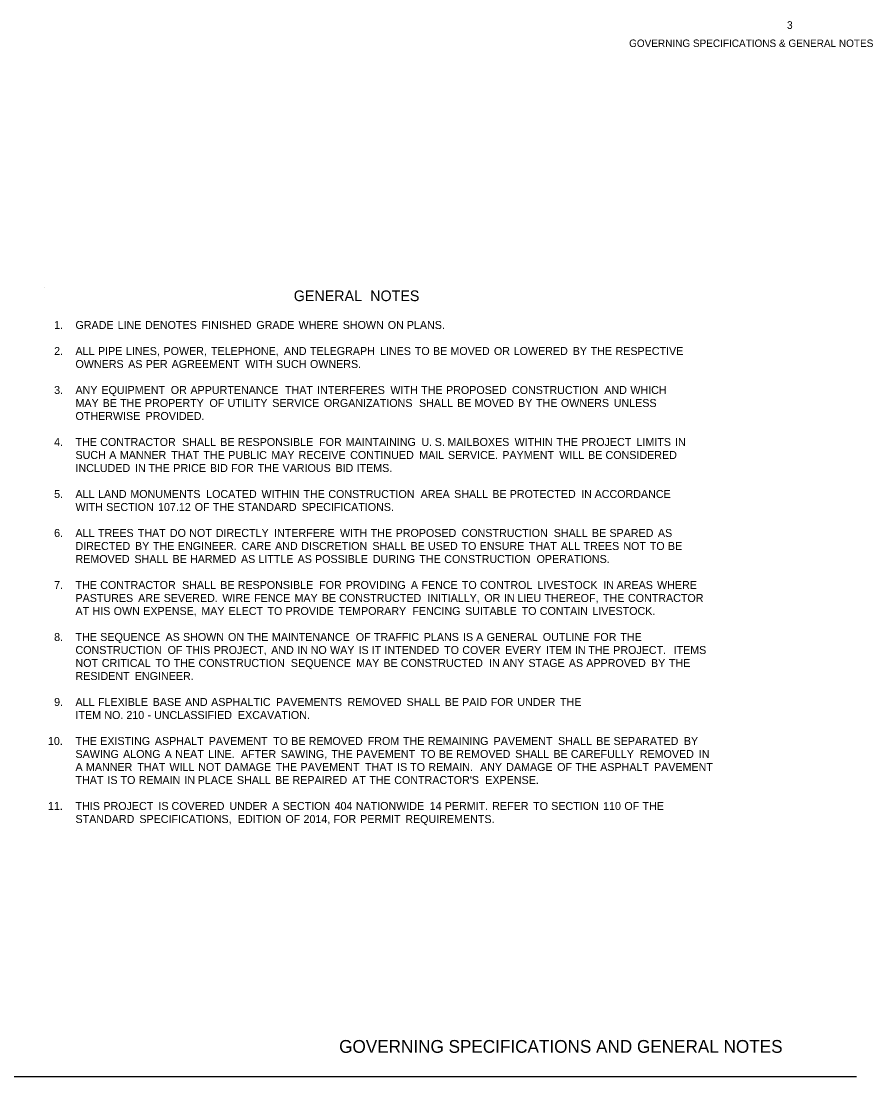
# Model space of a CAD drawing. Extents: x 1334737.6 to 1334769.5, y 402732.2 to 402752.6.
# Drawn here: x 1334753.53 to 1334769.49, y 402732.19 to 402751.98 of the extents above; entities that cross this region are included whole.
import ezdxf

# ---------------------------------------------------------------- set-up
doc = ezdxf.new("R2010")
doc.units = 0
doc.layers.add('Default', color=7, linetype='Continuous')
doc.layers.add('R_No Plot', color=7, linetype='Continuous')

msp = doc.modelspace()

# ---------------------------------------------------------------- linework, layer by layer
at = {"layer": 'Default'}
msp.add_line((1334753.96, 402746.996), (1334753.96, 402746.996), dxfattribs=at)
at = {"layer": 'R_No Plot'}
msp.add_line((1334769.182, 402732.187), (1334737.564, 402732.187), dxfattribs=at)

# ---------------------------------------------------------------- texts
at = {"layer": 'Default'}
for s, height, p in [('GENERAL', 0.2, (1334758.636, 402746.732)), (' NOTES', 0.2, (1334759.994, 402746.732)), ('1.', 0.15, (1334754.145, 402746.21)), ('GRADE', 0.15, (1334754.545, 402746.21)), (' LINE', 0.15, (1334755.279, 402746.21)), (' DENOTES', 0.15, (1334755.792, 402746.21)), (' FINISHED', 0.15, (1334756.853, 402746.21)), (' GRADE', 0.15, (1334757.878, 402746.21)), (' WHERE', 0.15, (1334758.67, 402746.21)), (' SHOWN', 0.15, (1334759.498, 402746.21)), (' ON', 0.15, (1334760.342, 402746.21)), (' PLANS.', 0.15, (1334760.698, 402746.21)), ('2.', 0.15, (1334754.145, 402745.722)), ('ALL', 0.15, (1334754.545, 402745.722)), (' PIPE', 0.15, (1334754.911, 402745.722)), (' LINES,', 0.15, (1334755.435, 402745.722)), (' POWER,', 0.15, (1334756.139, 402745.722)), (' TELEPHONE,', 0.15, (1334757.028, 402745.722)), (' AND', 0.15, (1334758.396, 402745.722)), (' TELEGRAPH', 0.15, (1334758.885, 402745.722)), (' LINES', 0.15, (1334760.196, 402745.722)), (' TO', 0.15, (1334760.849, 402745.722)), (' BE', 0.15, (1334761.189, 402745.722)), (' MOVED', 0.15, (1334761.516, 402745.722)), (' OR', 0.15, (1334762.331, 402745.722)), (' LOWERED', 0.15, (1334762.701, 402745.722)), (' BY', 0.15, (1334763.808, 402745.722)), (' THE', 0.15, (1334764.144, 402745.722)), (' RESPECTIVE', 0.15, (1334764.61, 402745.722)), ('OWNERS', 0.15, (1334754.545, 402745.478)), (' AS', 0.15, (1334755.477, 402745.478)), (' PER', 0.15, (1334755.804, 402745.478)), (' AGREEMENT', 0.15, (1334756.291, 402745.478)), (' WITH', 0.15, (1334757.672, 402745.478)), (' SUCH', 0.15, (1334758.249, 402745.478)), (' OWNERS.', 0.15, (1334758.884, 402745.478)), ('3.', 0.15, (1334754.145, 402744.991)), ('ANY', 0.15, (1334754.545, 402744.991)), (' EQUIPMENT', 0.15, (1334754.975, 402744.991)), (' OR', 0.15, (1334756.275, 402744.991)), (' APPURTENANCE', 0.15, (1334756.644, 402744.991)), (' THAT', 0.15, (1334758.415, 402744.991)), (' INTERFERES', 0.15, (1334759.017, 402744.991)), (' WITH', 0.15, (1334760.391, 402744.991)), (' THE', 0.15, (1334760.968, 402744.991)), (' PROPOSED', 0.15, (1334761.434, 402744.991)), (' CONSTRUCTION', 0.15, (1334762.669, 402744.991)), (' AND', 0.15, (1334764.399, 402744.991)), (' WHICH', 0.15, (1334764.888, 402744.991)), ('MAY', 0.15, (1334754.545, 402744.747)), (' BE', 0.15, (1334754.998, 402744.747)), (' THE', 0.15, (1334755.325, 402744.747)), (' PROPERTY', 0.15, (1334755.791, 402744.747)), (' OF', 0.15, (1334757, 402744.747)), (' UTILITY', 0.15, (1334757.34, 402744.747)), (' SERVICE', 0.15, (1334758.177, 402744.747)), (' ORGANIZATIONS', 0.15, (1334759.144, 402744.747)), (' SHALL', 0.15, (1334760.927, 402744.747)), (' BE', 0.15, (1334761.641, 402744.747)), (' MOVED', 0.15, (1334761.968, 402744.747)), (' BY', 0.15, (1334762.784, 402744.747)), (' THE', 0.15, (1334763.12, 402744.747)), (' OWNERS', 0.15, (1334763.586, 402744.747)), (' UNLESS', 0.15, (1334764.576, 402744.747)), ('OTHERWISE', 0.15, (1334754.545, 402744.503)), (' PROVIDED.', 0.15, (1334755.803, 402744.503)), ('4.', 0.15, (1334754.145, 402744.016)), ('THE', 0.15, (1334754.545, 402744.016)), (' CONTRACTOR', 0.15, (1334754.953, 402744.016)), (' SHALL', 0.15, (1334756.487, 402744.016)), (' BE', 0.15, (1334757.202, 402744.016)), (' RESPONSIBLE', 0.15, (1334757.529, 402744.016)), (' FOR', 0.15, (1334759.055, 402744.016)), (' MAINTAINING', 0.15, (1334759.553, 402744.016)), (' U.', 0.15, (1334760.972, 402744.016)), (' S.', 0.15, (1334761.222, 402744.016)), (' MAILBOXES', 0.15, (1334761.46, 402744.016)), (' WITHIN', 0.15, (1334762.718, 402744.016)), (' THE', 0.15, (1334763.504, 402744.016)), (' PROJECT', 0.15, (1334763.97, 402744.016)), (' LIMITS', 0.15, (1334765.003, 402744.016)), (' IN', 0.15, (1334765.725, 402744.016)), ('SUCH', 0.15, (1334754.545, 402743.772)), (' A', 0.15, (1334755.122, 402743.772)), (' MANNER', 0.15, (1334755.321, 402743.772)), (' THAT', 0.15, (1334756.284, 402743.772)), (' THE', 0.15, (1334756.886, 402743.772)), (' PUBLIC', 0.15, (1334757.352, 402743.772)), (' MAY', 0.15, (1334758.159, 402743.772)), (' RECEIVE', 0.15, (1334758.67, 402743.772)), (' CONTINUED', 0.15, (1334759.637, 402743.772)), (' MAIL', 0.15, (1334760.93, 402743.772)), (' SERVICE.', 0.15, (1334761.47, 402743.772)), (' PAYMENT', 0.15, (1334762.488, 402743.772)), (' WILL', 0.15, (1334763.555, 402743.772)), (' BE', 0.15, (1334764.095, 402743.772)), (' CONSIDERED', 0.15, (1334764.422, 402743.772)), ('INCLUDED', 0.15, (1334754.545, 402743.528)), (' IN', 0.15, (1334755.605, 402743.528)), (' THE', 0.15, (1334755.856, 402743.528)), (' PRICE', 0.15, (1334756.322, 402743.528)), (' BID', 0.15, (1334757.01, 402743.528)), (' FOR', 0.15, (1334757.406, 402743.528)), (' THE', 0.15, (1334757.904, 402743.528)), (' VARIOUS', 0.15, (1334758.37, 402743.528)), (' BID', 0.15, (1334759.361, 402743.528)), (' ITEMS.', 0.15, (1334759.757, 402743.528)), ('5.', 0.15, (1334754.145, 402743.041)), ('ALL', 0.15, (1334754.545, 402743.041)), (' LAND', 0.15, (1334754.911, 402743.041)), (' MONUMENTS', 0.15, (1334755.517, 402743.041)), (' LOCATED', 0.15, (1334756.938, 402743.041)), (' WITHIN', 0.15, (1334757.975, 402743.041)), (' THE', 0.15, (1334758.761, 402743.041)), (' CONSTRUCTION', 0.15, (1334759.227, 402743.041)), (' AREA', 0.15, (1334760.957, 402743.041)), (' SHALL', 0.15, (1334761.586, 402743.041)), (' BE', 0.15, (1334762.301, 402743.041)), (' PROTECTED', 0.15, (1334762.627, 402743.041)), (' IN', 0.15, (1334763.967, 402743.041)), (' ACCORDANCE', 0.15, (1334764.218, 402743.041)), ('WITH', 0.15, (1334754.545, 402742.797)), (' SECTION', 0.15, (1334755.064, 402742.797)), (' 107.12', 0.15, (1334756.036, 402742.797)), (' OF', 0.15, (1334756.724, 402742.797)), (' THE', 0.15, (1334757.064, 402742.797)), (' STANDARD', 0.15, (1334757.53, 402742.797)), (' SPECIFICATIONS.', 0.15, (1334758.73, 402742.797)), ('6.', 0.15, (1334754.145, 402742.31)), ('ALL', 0.15, (1334754.545, 402742.31)), (' TREES', 0.15, (1334754.911, 402742.31)), (' THAT', 0.15, (1334755.657, 402742.31)), (' DO', 0.15, (1334756.258, 402742.31)), (' NOT', 0.15, (1334756.621, 402742.31)), (' DIRECTLY', 0.15, (1334757.118, 402742.31)), (' INTERFERE', 0.15, (1334758.211, 402742.31)), (' WITH', 0.15, (1334759.446, 402742.31)), (' THE', 0.15, (1334760.022, 402742.31)), (' PROPOSED', 0.15, (1334760.489, 402742.31)), (' CONSTRUCTION', 0.15, (1334761.724, 402742.31)), (' SHALL', 0.15, (1334763.453, 402742.31)), (' BE', 0.15, (1334764.168, 402742.31)), (' SPARED', 0.15, (1334764.495, 402742.31)), (' AS', 0.15, (1334765.404, 402742.31)), ('DIRECTED', 0.15, (1334754.545, 402742.066)), (' BY', 0.15, (1334755.605, 402742.066)), (' THE', 0.15, (1334755.942, 402742.066)), (' ENGINEER.', 0.15, (1334756.408, 402742.066)), (' CARE', 0.15, (1334757.601, 402742.066)), (' AND', 0.15, (1334758.23, 402742.066)), (' DISCRETION', 0.15, (1334758.72, 402742.066)), (' SHALL', 0.15, (1334760.053, 402742.066)), (' BE', 0.15, (1334760.768, 402742.066)), (' USED', 0.15, (1334761.095, 402742.066)), (' TO', 0.15, (1334761.724, 402742.066)), (' ENSURE', 0.15, (1334762.064, 402742.066)), (' THAT', 0.15, (1334762.985, 402742.066)), (' ALL', 0.15, (1334763.586, 402742.066)), (' TREES', 0.15, (1334764.01, 402742.066)), (' NOT', 0.15, (1334764.756, 402742.066)), (' TO', 0.15, (1334765.252, 402742.066)), (' BE', 0.15, (1334765.592, 402742.066)), ('REMOVED', 0.15, (1334754.545, 402741.822)), (' SHALL', 0.15, (1334755.594, 402741.822)), (' BE', 0.15, (1334756.309, 402741.822)), (' HARMED', 0.15, (1334756.635, 402741.822)), (' AS', 0.15, (1334757.591, 402741.822)), (' LITTLE', 0.15, (1334757.917, 402741.822)), (' AS', 0.15, (1334758.652, 402741.822)), (' POSSIBLE', 0.15, (1334758.978, 402741.822)), (' DURING', 0.15, (1334760.062, 402741.822)), (' THE', 0.15, (1334760.934, 402741.822)), (' CONSTRUCTION', 0.15, (1334761.4, 402741.822)), (' OPERATIONS.', 0.15, (1334763.13, 402741.822)), ('7.', 0.15, (1334754.145, 402741.335)), ('THE', 0.15, (1334754.545, 402741.335)), (' CONTRACTOR', 0.15, (1334754.953, 402741.335)), (' SHALL', 0.15, (1334756.487, 402741.335)), (' BE', 0.15, (1334757.202, 402741.335)), (' RESPONSIBLE', 0.15, (1334757.529, 402741.335)), (' FOR', 0.15, (1334759.055, 402741.335)), (' PROVIDING', 0.15, (1334759.553, 402741.335)), (' A', 0.15, (1334760.774, 402741.335)), (' FENCE', 0.15, (1334760.973, 402741.335)), (' TO', 0.15, (1334761.73, 402741.335)), (' CONTROL', 0.15, (1334762.07, 402741.335)), (' LIVESTOCK', 0.15, (1334763.146, 402741.335)), (' IN', 0.15, (1334764.38, 402741.335)), (' AREAS', 0.15, (1334764.63, 402741.335)), (' WHERE', 0.15, (1334765.388, 402741.335)), ('PASTURES', 0.15, (1334754.545, 402741.091)), (' ARE', 0.15, (1334755.664, 402741.091)), (' SEVERED.', 0.15, (1334756.142, 402741.091)), (' WIRE', 0.15, (1334757.242, 402741.091)), (' FENCE', 0.15, (1334757.836, 402741.091)), (' MAY', 0.15, (1334758.594, 402741.091)), (' BE', 0.15, (1334759.105, 402741.091)), (' CONSTRUCTED', 0.15, (1334759.431, 402741.091)), (' INITIALLY,', 0.15, (1334761.085, 402741.091)), (' OR', 0.15, (1334762.15, 402741.091)), (' IN', 0.15, (1334762.519, 402741.091)), (' LIEU', 0.15, (1334762.77, 402741.091)), (' THEREOF,', 0.15, (1334763.277, 402741.091)), (' THE', 0.15, (1334764.376, 402741.091)), (' CONTRACTOR', 0.15, (1334764.843, 402741.091)), ('AT', 0.15, (1334754.545, 402740.847)), (' HIS', 0.15, (1334754.809, 402740.847)), (' OWN', 0.15, (1334755.205, 402740.847)), (' EXPENSE,', 0.15, (1334755.759, 402740.847)), (' MAY', 0.15, (1334756.847, 402740.847)), (' ELECT', 0.15, (1334757.358, 402740.847)), (' TO', 0.15, (1334758.087, 402740.847)), (' PROVIDE', 0.15, (1334758.427, 402740.847)), (' TEMPORARY', 0.15, (1334759.417, 402740.847)), (' FENCING', 0.15, (1334760.802, 402740.847)), (' SUITABLE', 0.15, (1334761.79, 402740.847)), (' TO', 0.15, (1334762.85, 402740.847)), (' CONTAIN', 0.15, (1334763.19, 402740.847)), (' LIVESTOCK.', 0.15, (1334764.175, 402740.847)), ('8.', 0.15, (1334754.145, 402740.36)), ('THE', 0.15, (1334754.545, 402740.36)), (' SEQUENCE', 0.15, (1334754.953, 402740.36)), (' AS', 0.15, (1334756.177, 402740.36)), (' SHOWN', 0.15, (1334756.504, 402740.36)), (' ON', 0.15, (1334757.348, 402740.36)), (' THE', 0.15, (1334757.703, 402740.36)), (' MAINTENANCE', 0.15, (1334758.17, 402740.36)), (' OF', 0.15, (1334759.742, 402740.36)), (' TRAFFIC', 0.15, (1334760.082, 402740.36)), (' PLANS', 0.15, (1334761.017, 402740.36)), (' IS', 0.15, (1334761.751, 402740.36)), (' A', 0.15, (1334761.997, 402740.36)), (' GENERAL', 0.15, (1334762.195, 402740.36)), (' OUTLINE', 0.15, (1334763.247, 402740.36)), (' FOR', 0.15, (1334764.203, 402740.36)), (' THE', 0.15, (1334764.701, 402740.36)), ('CONSTRUCTION', 0.15, (1334754.545, 402740.116)), (' OF', 0.15, (1334756.216, 402740.116)), (' THIS', 0.15, (1334756.556, 402740.116)), (' PROJECT,', 0.15, (1334757.081, 402740.116)), (' AND', 0.15, (1334758.157, 402740.116)), (' IN', 0.15, (1334758.646, 402740.116)), (' NO', 0.15, (1334758.897, 402740.116)), (' WAY', 0.15, (1334759.26, 402740.116)), (' IS', 0.15, (1334759.794, 402740.116)), (' IT', 0.15, (1334760.04, 402740.116)), (' INTENDED', 0.15, (1334760.28, 402740.116)), (' TO', 0.15, (1334761.398, 402740.116)), (' COVER', 0.15, (1334761.738, 402740.116)), (' EVERY', 0.15, (1334762.539, 402740.116)), (' ITEM', 0.15, (1334763.306, 402740.116)), (' IN', 0.15, (1334763.849, 402740.116)), (' THE', 0.15, (1334764.1, 402740.116)), (' PROJECT.', 0.15, (1334764.566, 402740.116)), ('  ITEMS', 0.15, (1334765.642, 402740.116)), ('NOT', 0.15, (1334754.545, 402739.872)), (' CRITICAL', 0.15, (1334754.983, 402739.872)), (' TO', 0.15, (1334755.989, 402739.872)), (' THE', 0.15, (1334756.329, 402739.872)), (' CONSTRUCTION', 0.15, (1334756.795, 402739.872)), (' SEQUENCE', 0.15, (1334758.525, 402739.872)), (' MAY', 0.15, (1334759.748, 402739.872)), (' BE', 0.15, (1334760.259, 402739.872)), (' CONSTRUCTED', 0.15, (1334760.586, 402739.872)), (' IN', 0.15, (1334762.24, 402739.872)), (' ANY', 0.15, (1334762.49, 402739.872)), (' STAGE', 0.15, (1334762.978, 402739.872)), (' AS', 0.15, (1334763.735, 402739.872)), (' APPROVED', 0.15, (1334764.062, 402739.872)), (' BY', 0.15, (1334765.274, 402739.872)), (' THE', 0.15, (1334765.61, 402739.872)), ('RESIDENT', 0.15, (1334754.545, 402739.628)), (' ENGINEER.', 0.15, (1334755.601, 402739.628)), ('9.', 0.15, (1334754.145, 402739.141)), ('ALL', 0.15, (1334754.545, 402739.141)), (' FLEXIBLE', 0.15, (1334754.911, 402739.141)), (' BASE', 0.15, (1334755.936, 402739.141)), (' AND', 0.15, (1334756.542, 402739.141)), (' ASPHALTIC', 0.15, (1334757.032, 402739.141)), (' PAVEMENTS', 0.15, (1334758.247, 402739.141)), (' REMOVED', 0.15, (1334759.587, 402739.141)), (' SHALL', 0.15, (1334760.694, 402739.141)), (' BE', 0.15, (1334761.408, 402739.141)), (' PAID', 0.15, (1334761.735, 402739.141)), (' FOR', 0.15, (1334762.271, 402739.141)), (' UNDER', 0.15, (1334762.769, 402739.141)), (' THE', 0.15, (1334763.57, 402739.141)), ('ITEM', 0.15, (1334754.545, 402738.897)), (' NO.', 0.15, (1334755.03, 402738.897)), (' 210', 0.15, (1334755.443, 402738.897)), (' -', 0.15, (1334755.84, 402738.897)), (' UNCLASSIFIED', 0.15, (1334755.962, 402738.897)), (' EXCAVATION.', 0.15, (1334757.534, 402738.897)), ('10.', 0.15, (1334754.029, 402738.41)), ('THE', 0.15, (1334754.545, 402738.41)), (' EXISTING', 0.15, (1334754.953, 402738.41)), (' ASPHALT', 0.15, (1334755.977, 402738.41)), (' PAVEMENT', 0.15, (1334756.986, 402738.41)), (' TO', 0.15, (1334758.193, 402738.41)), (' BE', 0.15, (1334758.533, 402738.41)), (' REMOVED', 0.15, (1334758.859, 402738.41)), (' FROM', 0.15, (1334759.966, 402738.41)), (' THE', 0.15, (1334760.626, 402738.41)), (' REMAINING', 0.15, (1334761.092, 402738.41)), (' PAVEMENT', 0.15, (1334762.325, 402738.41)), (' SHALL', 0.15, (1334763.532, 402738.41)), (' BE', 0.15, (1334764.247, 402738.41)), (' SEPARATED', 0.15, (1334764.573, 402738.41)), (' BY', 0.15, (1334765.89, 402738.41)), ('SAWING', 0.15, (1334754.545, 402738.166)), (' ALONG', 0.15, (1334755.382, 402738.166)), (' A', 0.15, (1334756.161, 402738.166)), (' NEAT', 0.15, (1334756.359, 402738.166)), (' LINE.', 0.15, (1334756.972, 402738.166)), ('  AFTER', 0.15, (1334757.536, 402738.166)), (' SAWING,', 0.15, (1334758.337, 402738.166)), (' THE', 0.15, (1334759.285, 402738.166)), (' PAVEMENT', 0.15, (1334759.751, 402738.166)), (' TO', 0.15, (1334760.958, 402738.166)), (' BE', 0.15, (1334761.298, 402738.166)), (' REMOVED', 0.15, (1334761.625, 402738.166)), (' SHALL', 0.15, (1334762.731, 402738.166)), (' BE', 0.15, (1334763.446, 402738.166)), (' CAREFULLY', 0.15, (1334763.773, 402738.166)), (' REMOVED', 0.15, (1334765.064, 402738.166)), (' IN', 0.15, (1334766.171, 402738.166)), ('A', 0.15, (1334754.545, 402737.922)), (' MANNER', 0.15, (1334754.685, 402737.922)), (' THAT', 0.15, (1334755.649, 402737.922)), (' WILL', 0.15, (1334756.25, 402737.922)), (' NOT', 0.15, (1334756.79, 402737.922)), (' DAMAGE', 0.15, (1334757.287, 402737.922)), (' THE', 0.15, (1334758.242, 402737.922)), (' PAVEMENT', 0.15, (1334758.708, 402737.922)), (' THAT', 0.15, (1334759.915, 402737.922)), (' IS', 0.15, (1334760.517, 402737.922)), (' TO', 0.15, (1334760.762, 402737.922)), (' REMAIN.', 0.15, (1334761.102, 402737.922)), ('  ANY', 0.15, (1334762.015, 402737.922)), (' DAMAGE', 0.15, (1334762.561, 402737.922)), (' OF', 0.15, (1334763.516, 402737.922)), (' THE', 0.15, (1334763.856, 402737.922)), (' ASPHALT', 0.15, (1334764.322, 402737.922)), (' PAVEMENT', 0.15, (1334765.331, 402737.922)), ('THAT', 0.15, (1334754.545, 402737.678)), (' IS', 0.15, (1334755.088, 402737.678)), (' TO', 0.15, (1334755.334, 402737.678)), (' REMAIN', 0.15, (1334755.673, 402737.678)), (' IN', 0.15, (1334756.53, 402737.678)), (' PLACE', 0.15, (1334756.78, 402737.678)), (' SHALL', 0.15, (1334757.515, 402737.678)), (' BE', 0.15, (1334758.229, 402737.678)), (' REPAIRED', 0.15, (1334758.556, 402737.678)), (' AT', 0.15, (1334759.675, 402737.678)), (' THE', 0.15, (1334759.996, 402737.678)), (" CONTRACTOR'S", 0.15, (1334760.463, 402737.678)), (' EXPENSE.', 0.15, (1334762.169, 402737.678)), ('11.', 0.15, (1334754.029, 402737.191)), ('THIS', 0.15, (1334754.545, 402737.191)), (' PROJECT', 0.15, (1334755.012, 402737.191)), (' IS', 0.15, (1334756.044, 402737.191)), (' COVERED', 0.15, (1334756.289, 402737.191)), (' UNDER', 0.15, (1334757.373, 402737.191)), (' A', 0.15, (1334758.173, 402737.191)), (' SECTION', 0.15, (1334758.372, 402737.191)), (' 404', 0.15, (1334759.345, 402737.191)), (' NATIONWIDE', 0.15, (1334759.742, 402737.191)), (' 14', 0.15, (1334761.128, 402737.191)), (' PERMIT.', 0.15, (1334761.409, 402737.191)), (' REFER', 0.15, (1334762.299, 402737.191)), (' TO', 0.15, (1334763.065, 402737.191)), (' SECTION', 0.15, (1334763.405, 402737.191)), (' 110', 0.15, (1334764.377, 402737.191)), (' OF', 0.15, (1334764.775, 402737.191)), (' THE', 0.15, (1334765.115, 402737.191)), ('STANDARD', 0.15, (1334754.545, 402736.947)), (' SPECIFICATIONS,', 0.15, (1334755.687, 402736.947)), (' EDITION', 0.15, (1334757.532, 402736.947)), (' OF', 0.15, (1334758.423, 402736.947)), (' 2014,', 0.15, (1334758.762, 402736.947)), (' FOR', 0.15, (1334759.326, 402736.947)), (' PERMIT', 0.15, (1334759.824, 402736.947)), (' REQUIREMENTS.', 0.15, (1334760.67, 402736.947))]:
    msp.add_text(s, height=height, dxfattribs=at).set_placement(p)
at = {"layer": 'R_No Plot'}
for s, height, p in [('3', 0.144, (1334767.878, 402751.836)), ('GOVERNING SPECIFICATIONS AND GENERAL NOTES', 0.24, (1334759.486, 402732.638))]:
    msp.add_text(s, height=height, dxfattribs=at).set_placement(p)
msp.add_text('GOVERNING SPECIFICATIONS & GENERAL NOTES', height=0.14, rotation=360, dxfattribs=at).set_placement((1334764.92, 402751.497))

doc.saveas('drawing.dxf')
